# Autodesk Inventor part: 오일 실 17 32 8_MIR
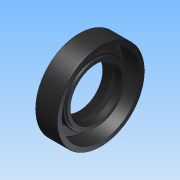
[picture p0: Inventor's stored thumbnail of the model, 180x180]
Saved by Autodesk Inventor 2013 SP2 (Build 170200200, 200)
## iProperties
Created: 2026-07
Part Number: 오일 실 17 32 8_MIR
Material: Generic
Document SubType Name: Modeling
Designer: aa
Density: 1 g/cm^3
Author: aa
변환 표준: STEP AP214IS
전처리기: Build: 200, Release: 2013 SP2 Update 6 - Date: Thu 07/17/2014
전송 단위: 밀리미터
불확실성: 0.01
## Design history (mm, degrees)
derived "오일 실 17 32 8.ipt"
feature "Solid1::오일 실 17 32 8.ipt" dims "d0" = 10
tag "피쳐 태그1"
node "솔리드1"
